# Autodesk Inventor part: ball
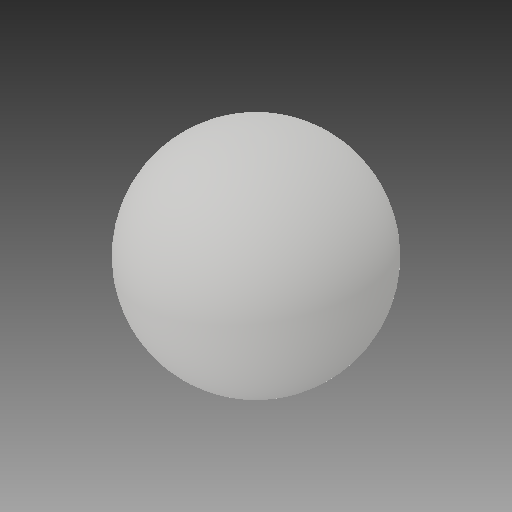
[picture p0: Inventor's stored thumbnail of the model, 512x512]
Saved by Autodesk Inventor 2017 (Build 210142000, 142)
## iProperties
Created: 2020-03
Part Number: ball
Material: Generic
Document SubType Name: Modeling
Designer: user
Density: 1 g/cm^3
Appearance: Default
Author: user
Revision Number: ANY
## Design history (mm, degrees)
feature "Revolve1"
body "Solid1"
